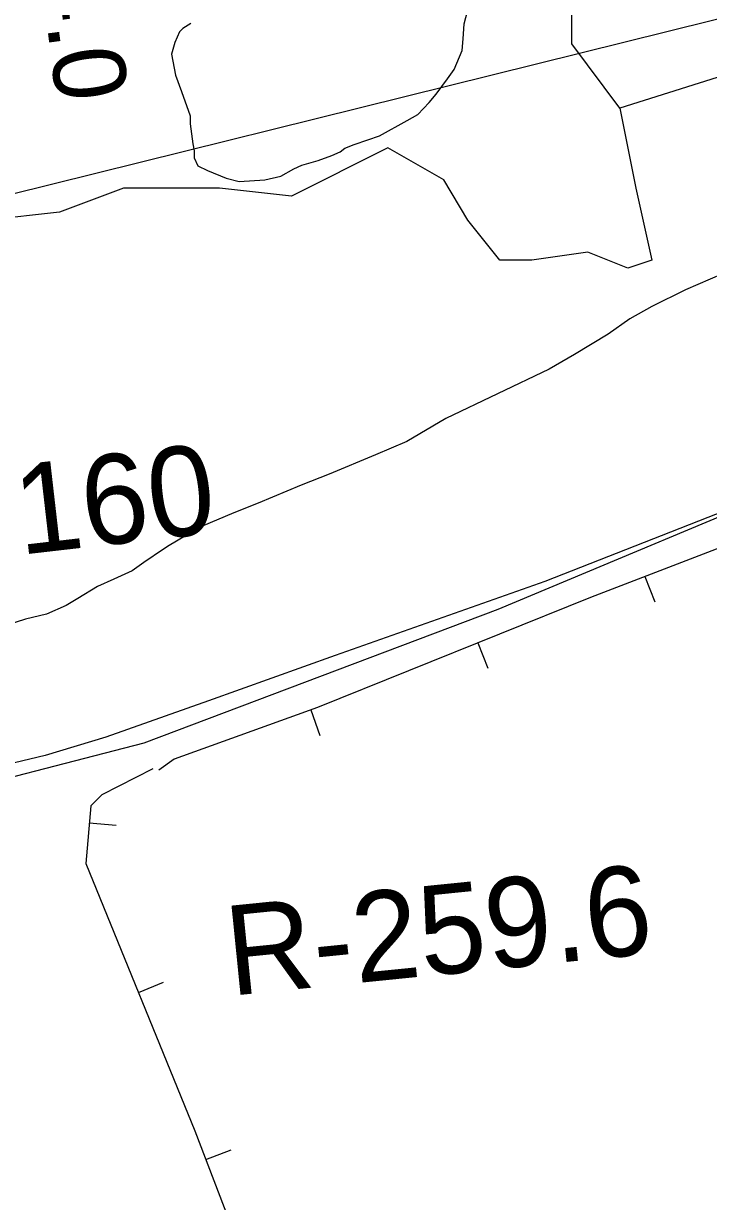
# Model space of a CAD drawing. Extents: x 3250478 to 3288318, y 788638 to 816472.
# Drawn here: x 3277589 to 3278223, y 803037 to 804127 of the extents above; entities that cross this region are included whole.
import ezdxf

# ---------------------------------------------------------------- set-up
doc = ezdxf.new("R2010")
doc.units = 0
for name, color, linetype in [('V-BORW-LINE', 7, 'Continuous'), ('V-RIVR-RANG', 7, 'Continuous'), ('V-RIVR-RANG-IDEN', 7, 'Continuous'), ('V-ROAD-CNTR', 7, 'Continuous'), ('V-SITE-VEGE', 7, 'Continuous'), ('V-TOPO-SHOR', 7, 'Continuous'), ('V-UTIL-LINE', 7, 'Continuous')]:
    doc.layers.add(name, color=color, linetype=linetype)

msp = doc.modelspace()

# ---------------------------------------------------------------- linework, layer by layer
at = {"layer": 'V-BORW-LINE'}
for p, q in [((3278164.6, 803615.5), (3278173.6, 803592.2)), ((3278009.8, 803554), (3278019.1, 803530.8)), ((3277855.2, 803492), (3277863.6, 803468.5)), ((3277650.3, 803387.4), (3277675.2, 803385.3)), ((3277695.8, 803230.5), (3277719, 803240)), ((3277758.1, 803076), (3277781.5, 803084.9))]:
    msp.add_line(p, q, dxfattribs=at)
for points in [[(3278274.5, 803657.9), (3278114.3, 803596.1), (3277861.6, 803494.3), (3277729, 803446.5), (3277714.7, 803436.3)], [(3278274.5, 803657.9), (3278114.3, 803596.1), (3277861.6, 803494.3), (3277729, 803446.5), (3277714.7, 803436.3)], [(3277709.1, 803437.5), (3277661.8, 803413.3), (3277651.6, 803403.3), (3277647.1, 803350), (3277748, 803102.6), (3277814.2, 802929), (3277923, 802615.5), (3278019.3, 802378.6), (3278144, 802059.4), (3278237.8, 801798.7)], [(3277709.1, 803437.5), (3277661.8, 803413.3), (3277651.6, 803403.3), (3277647.1, 803350), (3277748, 803102.6), (3277814.2, 802929), (3277923, 802615.5), (3278019.3, 802378.6), (3278144, 802059.4), (3278237.8, 801798.7)]]:
    msp.add_lwpolyline(points, dxfattribs=at)
at = {"layer": 'V-ROAD-CNTR'}
for points in [[(3278330.5, 803712.4), (3278071.8, 803610.8), (3277877.9, 803542.4), (3277760.5, 803500.5), (3277665.5, 803466.7), (3277609.5, 803449.7), (3277566.7, 803439.7), (3277366.7, 803387.7), (3277346.3, 803375), (3277336.4, 803357.4), (3277336.4, 803334.5), (3277346.3, 803290.6), (3277379.2, 803066.6), (3277415.1, 802799), (3277438.2, 802529.4), (3277460.1, 802331.7), (3277473.4, 802040.2), (3277480.1, 801770.8), (3277492.8, 801679), (3277506.9, 801611.4), (3277520.6, 801531.3)], [(3277612.5, 801156.3), (3277539.9, 801504.7), (3277504.3, 801737.2), (3277487.3, 801991.8), (3277460.1, 802394), (3277422.8, 802784.4), (3277395.6, 802976.1), (3277361.7, 803183.2), (3277343, 803291.8), (3277343, 803330.9), (3277363.4, 803366.5), (3277397.3, 803388.6), (3277490.7, 803407.2), (3277701.1, 803461.6), (3278028.7, 803585.4), (3278332.5, 803712.5)]]:
    msp.add_lwpolyline(points, dxfattribs=at)
at = {"layer": 'V-SITE-VEGE'}
for p, q in [((3277997.2, 804127.1), (3278003.3, 804150.9)), ((3277744.4, 804127.3), (3277736.9, 804122.8)), ((3277996.3, 804113), (3277997.2, 804127.1)), ((3277733.8, 804119.5), (3277729.6, 804109.7)), ((3277736.9, 804122.8), (3277733.8, 804119.5)), ((3277729.6, 804109.7), (3277726.5, 804098.9)), ((3277995.4, 804102.2), (3277996.3, 804113)), ((3277726.5, 804098.9), (3277730.1, 804079.5)), ((3277988.1, 804084.8), (3277995.4, 804102.2)), ((3277981.8, 804076), (3277988.1, 804084.8)), ((3277730.1, 804079.5), (3277735.7, 804064.5)), ((3277971.2, 804061.8), (3277981.8, 804076)), ((3277735.7, 804064.5), (3277743.7, 804041.9)), ((3277964.9, 804054.2), (3277971.2, 804061.8)), ((3277954.3, 804043.2), (3277964.9, 804054.2)), ((3277743.7, 804041.9), (3277743.8, 804034.4)), ((3277918.9, 804023.2), (3277944.6, 804037.6)), ((3277944.6, 804037.6), (3277954.3, 804043.2)), ((3277743.8, 804034.4), (3277746.2, 804016)), ((3277746.2, 804016), (3277747.4, 804009.6)), ((3277895.3, 804015.2), (3277908.2, 804019.8)), ((3277908.2, 804019.8), (3277918.9, 804023.2)), ((3277747.4, 804009.6), (3277747.5, 804003.1)), ((3277862.1, 804000.6), (3277874.9, 804005.2)), ((3277874.9, 804005.2), (3277882.5, 804008.5)), ((3277882.5, 804008.5), (3277886.7, 804011.8)), ((3277886.7, 804011.8), (3277895.3, 804015.2)), ((3277747.5, 804003.1), (3277750.9, 803995.6)), ((3277750.9, 803995.6), (3277759.6, 803991.4)), ((3277839.5, 803992.7), (3277847, 803996.1)), ((3277847, 803996.1), (3277862.1, 804000.6)), ((3277759.6, 803991.4), (3277777, 803984.1)), ((3277777, 803984.1), (3277788.9, 803981.1)), ((3277812.7, 803982.6), (3277827.7, 803986)), ((3277827.7, 803986), (3277839.5, 803992.7)), ((3277788.9, 803981.1), (3277812.7, 803982.6)), ((3278262.1, 803906.7), (3278202.1, 803880.9)), ((3278202.1, 803880.9), (3278171, 803865.3)), ((3278171, 803865.3), (3278150.7, 803854.1)), ((3278150.7, 803854.1), (3278130.4, 803839.7)), ((3278130.4, 803839.7), (3278099.4, 803820.9)), ((3278099.4, 803820.9), (3278075.8, 803807.5)), ((3278075.8, 803807.5), (3277980.4, 803761.7)), ((3277980.4, 803761.7), (3277944.1, 803740.6)), ((3277944.1, 803740.6), (3277915.1, 803728.2)), ((3277915.1, 803728.2), (3277872.2, 803710.3)), ((3277846.4, 803700.1), (3277806.7, 803683.3)), ((3277872.2, 803710.3), (3277846.4, 803700.1)), ((3277806.7, 803683.3), (3277784.2, 803674.3)), ((3277784.2, 803674.3), (3277754.2, 803661.9)), ((3277746.6, 803658.5), (3277739.2, 803653)), ((3277754.2, 803661.9), (3277746.6, 803658.5)), ((3277739.2, 803653), (3277724.2, 803644.1)), ((3277718.9, 803640.8), (3277700.7, 803628.6)), ((3277724.2, 803644.1), (3277718.9, 803640.8)), ((3277700.7, 803628.6), (3277690, 803620.9)), ((3277672.9, 803613), (3277657.9, 803606.3)), ((3277690, 803620.9), (3277672.9, 803613)), ((3277657.9, 803606.3), (3277639.7, 803595.2)), ((3277639.7, 803595.2), (3277629, 803588.6)), ((3277610.7, 803580.7), (3277591.4, 803576.1)), ((3277629, 803588.6), (3277610.7, 803580.7)), ((3277591.4, 803576.1), (3277563.4, 803567))]:
    msp.add_line(p, q, dxfattribs=at)
at = {"layer": 'V-TOPO-SHOR'}
for points in [[(3278926.7, 804308.5), (3278578.5, 804204.7), (3278319.2, 804130.6), (3278259.9, 804086.2), (3278141.3, 804049.1), (3278141.3, 804049.1), (3278096.9, 804108.4), (3278096.9, 804175.1), (3278096.9, 804212.1), (3278089.5, 804264), (3278067.2, 804293.7), (3278037.6, 804323.3), (3278015.4, 804338.1)], [(3278141.3, 804049.1), (3278156.2, 803975), (3278171, 803908.4), (3278148.8, 803901), (3278111.7, 803915.8), (3278059.8, 803908.4), (3278030.2, 803908.4), (3278000.6, 803945.4), (3277978.3, 803982.5), (3277926.5, 804012.1), (3277837.6, 803967.6), (3277770.9, 803975), (3277682, 803975), (3277622.7, 803952.8), (3277556, 803945.4), (3277519, 803938), (3277407.8, 803908.4), (3277385.6, 803878.7), (3277378.2, 803878.7)]]:
    msp.add_lwpolyline(points, dxfattribs=at)
at = {"layer": 'V-UTIL-LINE'}
msp.add_lwpolyline([(3277371.3, 803918.1), (3278227.1, 804130.3), (3278966.1, 804313.1), (3279791.6, 804514.5), (3280404.5, 804671.4), (3280632.5, 804743.8), (3281799.4, 805040.2)], dxfattribs=at)

# ---------------------------------------------------------------- texts
at = {"layer": 'V-RIVR-RANG'}
msp.add_text('44.0', height=67, rotation=277.2383, dxfattribs=at).set_placement((3277598.5, 804225.2))
at = {"layer": 'V-RIVR-RANG-IDEN'}
for s, rotation, p in [('D-160', 6.5533, (3277469.8, 803622.1)), ('R-259.6', 5.7661, (3277781.2, 803227.4))]:
    msp.add_text(s, height=83, rotation=rotation, dxfattribs=at).set_placement(p)

doc.saveas('drawing.dxf')
